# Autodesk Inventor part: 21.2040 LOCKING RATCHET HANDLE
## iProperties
Created: 2007-01
Part Number: 21.2040 LOCKING RATCHET HANDLE
Document SubType Name: Modeling
Designer: Andy Moles
Material: ABS Plastic
Density: 1.06 g/cm^3
Author: Andy Moles
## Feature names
1. Base1
2. Chamfer1
